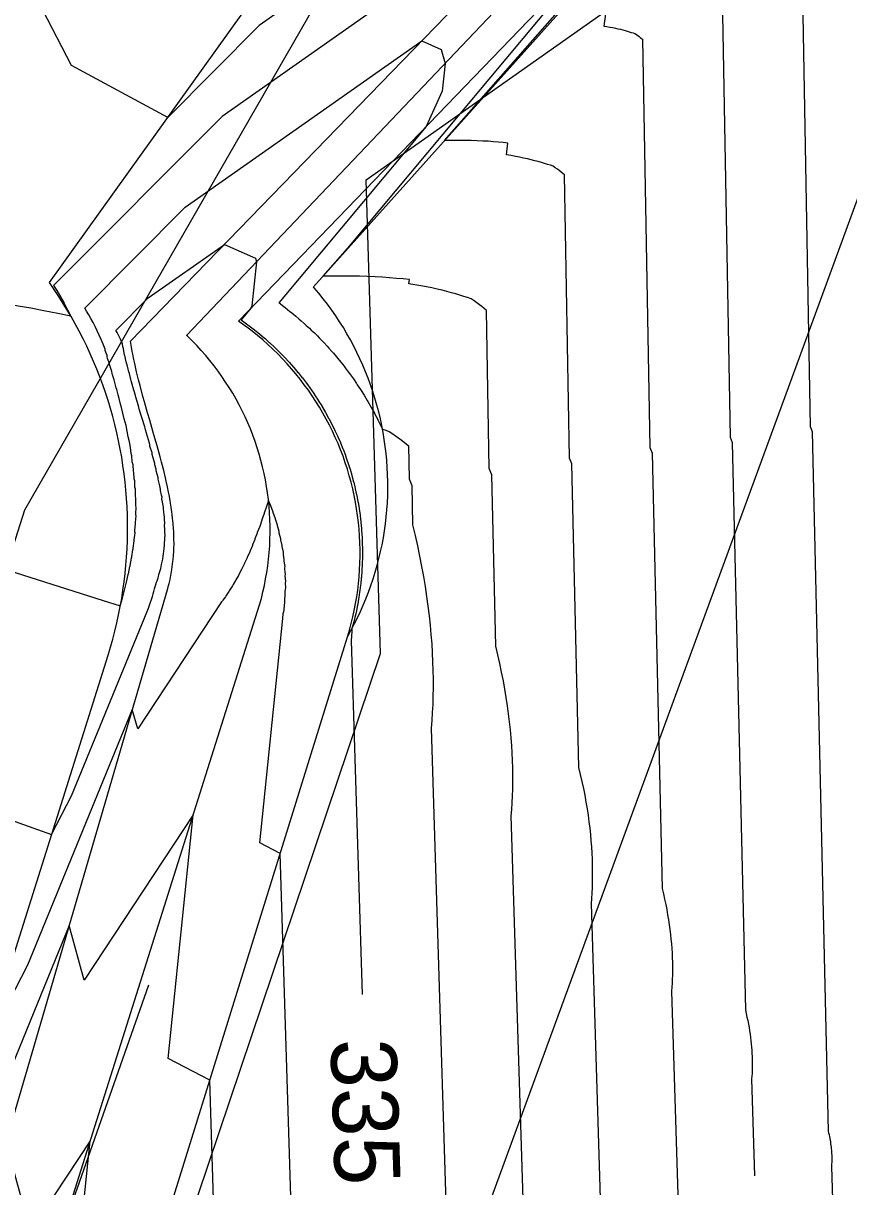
# Model space of a CAD drawing. Extents: x 487096 to 489566, y 221939 to 224454.
# Drawn here: x 488300.7 to 488340.9, y 223456 to 223512.7 of the extents above; entities that cross this region are included whole.
import ezdxf

# ---------------------------------------------------------------- set-up
doc = ezdxf.new("R2010")
doc.units = 0
for name, color, linetype in [('SV_BKLN_BKLN', 7, 'Continuous'), ('SV_BKLN_EARTH_TOP', 7, 'Continuous'), ('SV_PIPE_FLOW', 7, 'Continuous'), ('SV_SURF_INDEX_CONTOUR', 7, 'Continuous'), ('SV_SURF_INTER_CONTOUR', 7, 'Continuous'), ('SV_TREE_TREELN', 7, 'Continuous'), ('SV_WATR_INWETF', 7, 'Continuous'), ('SV_WATR_STREAM', 7, 'Continuous')]:
    doc.layers.add(name, color=color, linetype=linetype)

msp = doc.modelspace()

# ---------------------------------------------------------------- linework, layer by layer
at = {"layer": 'SV_BKLN_BKLN'}
for points in [[(488336.998, 223527.313), (488308.631, 223497.452)], [(488297.876, 223439.045), (488312.09, 223484.017), (488312.184, 223484.327), (488312.27, 223484.639), (488312.348, 223484.953), (488312.419, 223485.269), (488312.481, 223485.587), (488312.536, 223485.906), (488312.583, 223486.226), (488312.622, 223486.547), (488312.653, 223486.87), (488312.676, 223487.192), (488312.691, 223487.516), (488312.699, 223487.839), (488312.698, 223488.163), (488312.689, 223488.487), (488312.672, 223488.81), (488312.647, 223489.133), (488312.614, 223489.455), (488312.573, 223489.776), (488312.525, 223490.096), (488312.468, 223490.415), (488312.404, 223490.732), (488312.331, 223491.047), (488312.251, 223491.361), (488312.163, 223491.672), (488312.068, 223491.982), (488311.965, 223492.289), (488311.854, 223492.593), (488311.736, 223492.894), (488311.611, 223493.193), (488311.478, 223493.488), (488311.338, 223493.78), (488311.19, 223494.068), (488311.036, 223494.352), (488310.875, 223494.633), (488310.706, 223494.91), (488310.531, 223495.182), (488310.35, 223495.45), (488310.161, 223495.713), (488309.967, 223495.972), (488309.766, 223496.225), (488309.558, 223496.474), (488309.345, 223496.718), (488309.126, 223496.956), (488308.901, 223497.188), (488308.67, 223497.415), (488308.631, 223497.452)]]:
    msp.add_lwpolyline(points, dxfattribs=at)
at = {"layer": 'SV_BKLN_EARTH_TOP'}
for points in [[(488337.452, 223525.096), (488314.809, 223499.818)], [(488301.946, 223500.025), (488313.833, 223516.625)], [(488285.935, 223421.955), (488304.8, 223481.874), (488304.918, 223482.263), (488305.029, 223482.654), (488305.132, 223483.047), (488305.227, 223483.442), (488305.314, 223483.839), (488305.393, 223484.238), (488305.465, 223484.638), (488305.529, 223485.039), (488305.585, 223485.442), (488305.632, 223485.846), (488305.672, 223486.25), (488305.704, 223486.655), (488305.728, 223487.061), (488305.744, 223487.467), (488305.752, 223487.874), (488305.752, 223488.28), (488305.744, 223488.687), (488305.728, 223489.093), (488305.704, 223489.498), (488305.672, 223489.904), (488305.632, 223490.308), (488305.584, 223490.712), (488305.529, 223491.114), (488305.465, 223491.516), (488305.393, 223491.916), (488305.314, 223492.315), (488305.226, 223492.712), (488305.131, 223493.107), (488305.028, 223493.5), (488304.918, 223493.891), (488304.799, 223494.28), (488304.673, 223494.666), (488304.54, 223495.05), (488304.399, 223495.432), (488304.25, 223495.81), (488304.095, 223496.185), (488303.931, 223496.557), (488303.761, 223496.926), (488303.583, 223497.292), (488303.398, 223497.654), (488303.206, 223498.012), (488303.007, 223498.366), (488302.801, 223498.717), (488302.588, 223499.063), (488302.368, 223499.405), (488302.142, 223499.743), (488301.946, 223500.025)], [(488316.468, 223482.773), (488316.636, 223483.072), (488316.797, 223483.376), (488316.951, 223483.683), (488317.097, 223483.994), (488317.236, 223484.308), (488317.368, 223484.625), (488317.493, 223484.945), (488317.61, 223485.268), (488317.719, 223485.594), (488317.821, 223485.922), (488317.915, 223486.252), (488318.002, 223486.585), (488318.081, 223486.919), (488318.152, 223487.256), (488318.215, 223487.593), (488318.27, 223487.932), (488318.317, 223488.273), (488318.356, 223488.614), (488318.388, 223488.956), (488318.411, 223489.299), (488318.427, 223489.642), (488318.434, 223489.985), (488318.433, 223490.329), (488318.425, 223490.672), (488318.408, 223491.015), (488318.384, 223491.358), (488318.351, 223491.7), (488318.311, 223492.041), (488318.262, 223492.381), (488318.206, 223492.72), (488318.142, 223493.058), (488318.07, 223493.394), (488317.99, 223493.728), (488317.902, 223494.06), (488317.807, 223494.39), (488317.704, 223494.718), (488317.593, 223495.043), (488317.475, 223495.366), (488317.35, 223495.685), (488317.217, 223496.002), (488317.076, 223496.316), (488316.929, 223496.626), (488316.774, 223496.933), (488316.612, 223497.236), (488316.443, 223497.535), (488316.267, 223497.83), (488316.084, 223498.121), (488315.895, 223498.408), (488315.699, 223498.69), (488315.497, 223498.967), (488315.288, 223499.24), (488315.072, 223499.508), (488314.851, 223499.77), (488314.809, 223499.818)]]:
    msp.add_lwpolyline(points, dxfattribs=at)
at = {"layer": 'SV_PIPE_FLOW'}
msp.add_line((488306.766, 223465.787), (488301.799, 223451.631), dxfattribs=at)
at = {"layer": 'SV_SURF_INDEX_CONTOUR'}
for points in [[(488334.648, 223518.483), (488335.114, 223492.492), (488335.218, 223492.237), (488335.853, 223464.584), (488335.895, 223464.409), (488335.933, 223464.237), (488335.969, 223464.066), (488336.002, 223463.897), (488336.032, 223463.73), (488336.06, 223463.565), (488336.084, 223463.402), (488336.106, 223463.241), (488336.125, 223463.083), (488336.142, 223462.926), (488336.156, 223462.772), (488336.168, 223462.62), (488336.177, 223462.47), (488336.184, 223462.323), (488336.188, 223462.177), (488336.191, 223462.034), (488336.191, 223461.893), (488336.189, 223461.755), (488336.184, 223461.619), (488336.178, 223461.485), (488336.17, 223461.353), (488336.159, 223461.224), (488336.305, 223456.505)], [(488289.043, 223477.783), (488302.048, 223473.132), (488303.017, 223475.013), (488306.702, 223484.002), (488306.764, 223484.157), (488306.82, 223484.308), (488306.872, 223484.452), (488306.919, 223484.591), (488306.962, 223484.726), (488307, 223484.856), (488307.035, 223484.981), (488307.067, 223485.102), (488307.095, 223485.219), (488307.137, 223485.32), (488307.161, 223485.431), (488307.188, 223485.499), (488307.239, 223485.636), (488307.262, 223485.706), (488307.283, 223485.81), (488307.327, 223485.95), (488307.367, 223486.094), (488307.391, 223486.191), (488307.408, 223486.286), (488307.45, 223486.482), (488307.464, 223486.557), (488307.488, 223486.708), (488307.502, 223486.796), (488307.522, 223486.948), (488307.532, 223487.051), (488307.547, 223487.258), (488307.559, 223487.341), (488307.565, 223487.497), (488307.567, 223487.603), (488307.577, 223487.681), (488307.575, 223487.893), (488307.572, 223488), (488307.559, 223488.214), (488307.567, 223488.29), (488307.548, 223488.505), (488307.553, 223488.579), (488307.537, 223488.723), (488307.525, 223488.819), (488307.498, 223489.012), (488307.501, 223489.085), (488307.46, 223489.33), (488307.429, 223489.493), (488307.431, 223489.565), (488307.409, 223489.674), (488307.362, 223489.893), (488307.362, 223489.964), (488307.324, 223490.128), (488307.242, 223490.455), (488307.241, 223490.528), (488307.152, 223490.854), (488307.149, 223490.928), (488307.087, 223491.145), (488307.082, 223491.218), (488306.952, 223491.652), (488306.945, 223491.727), (488306.844, 223492.051), (488306.835, 223492.127), (488306.825, 223492.201), (488306.618, 223492.848), (488306.606, 223492.926), (488306.593, 223493.001), (488306.32, 223493.855), (488306.304, 223493.936), (488306.286, 223494.015), (488306.156, 223494.439), (488306.137, 223494.519), (488306.015, 223494.941), (488305.993, 223495.022), (488305.935, 223495.232), (488305.912, 223495.312), (488305.839, 223495.593), (488305.815, 223495.673), (488305.78, 223495.813), (488305.731, 223496.023), (488305.705, 223496.102), (488305.659, 223496.312), (488305.638, 223496.417), (488305.61, 223496.496), (488305.571, 223496.706), (488305.552, 223496.811), (488305.524, 223496.889), (488305.498, 223497.046), (488305.468, 223497.122), (488305.438, 223497.196), (488305.407, 223497.266), (488305.375, 223497.335), (488305.343, 223497.401), (488305.31, 223497.465), (488305.276, 223497.527), (488305.242, 223497.587), (488305.208, 223497.645), (488305.178, 223497.692), (488306.757, 223499.276), (488310.473, 223501.889), (488311.98, 223501.215), (488312.031, 223501.031), (488311.803, 223498.886), (488311.752, 223498.774), (488311.28, 223498.21), (488311.418, 223498.112), (488311.676, 223497.924), (488311.93, 223497.729), (488312.178, 223497.528), (488312.422, 223497.321), (488312.434, 223497.312), (488312.672, 223497.099), (488312.682, 223497.091), (488312.915, 223496.873), (488312.925, 223496.865), (488313.153, 223496.641), (488313.162, 223496.633), (488313.384, 223496.404), (488313.394, 223496.395), (488313.403, 223496.386), (488313.62, 223496.152), (488313.629, 223496.143), (488313.84, 223495.903), (488313.849, 223495.894), (488314.053, 223495.65), (488314.063, 223495.64), (488314.261, 223495.391), (488314.27, 223495.38), (488314.463, 223495.127), (488314.472, 223495.116), (488314.481, 223495.105), (488314.666, 223494.848), (488314.676, 223494.836), (488314.855, 223494.574), (488314.864, 223494.562), (488315.037, 223494.297), (488315.045, 223494.284), (488315.212, 223494.015), (488315.22, 223494.002), (488315.38, 223493.729), (488315.388, 223493.715), (488315.397, 223493.701), (488315.55, 223493.425), (488315.558, 223493.41), (488315.704, 223493.131), (488315.712, 223493.115), (488315.851, 223492.833), (488315.859, 223492.817), (488315.991, 223492.532), (488315.999, 223492.516), (488316.123, 223492.228), (488316.131, 223492.211), (488316.248, 223491.921), (488316.256, 223491.903), (488316.366, 223491.611), (488316.373, 223491.592), (488316.476, 223491.298), (488316.482, 223491.278), (488316.489, 223491.258), (488316.584, 223490.962), (488316.591, 223490.941), (488316.678, 223490.644), (488316.684, 223490.621), (488316.765, 223490.323), (488316.77, 223490.3), (488316.843, 223490.001), (488316.849, 223489.977), (488316.914, 223489.677), (488316.919, 223489.652), (488316.977, 223489.351), (488316.982, 223489.325), (488317.032, 223489.024), (488317.036, 223488.997), (488317.08, 223488.696), (488317.083, 223488.667), (488317.119, 223488.366), (488317.122, 223488.337), (488317.15, 223488.037), (488317.153, 223488.006), (488317.174, 223487.706), (488317.176, 223487.674), (488317.189, 223487.376), (488317.191, 223487.341), (488317.197, 223487.045), (488317.198, 223487.009), (488317.197, 223486.967), (488317.196, 223486.676), (488317.195, 223486.631), (488317.187, 223486.344), (488317.185, 223486.294), (488317.17, 223486.011), (488317.166, 223485.957), (488317.145, 223485.68), (488317.139, 223485.62), (488317.112, 223485.349), (488317.103, 223485.281), (488317.071, 223485.018), (488317.059, 223484.941), (488317.022, 223484.689), (488317.006, 223484.598), (488316.965, 223484.362), (488316.942, 223484.25), (488316.9, 223484.035), (488316.867, 223483.889), (488316.827, 223483.711), (488316.774, 223483.496), (488316.747, 223483.388), (488316.686, 223483.167), (488316.677, 223483.027), (488316.642, 223482.583), (488317.175, 223465.337)]]:
    msp.add_lwpolyline(points, dxfattribs=at)
at = {"layer": 'SV_SURF_INTER_CONTOUR'}
for points in [[(488329.706, 223521.724), (488310.366, 223508.123), (488302.146, 223499.88), (488302.3, 223499.635), (488302.48, 223499.335), (488302.657, 223499.024), (488302.832, 223498.701), (488302.988, 223498.398), (488302.35, 223498.527), (488301.679, 223498.657), (488301.038, 223498.776), (488300.425, 223498.885), (488299.926, 223498.969), (488299.677, 223499.552), (488291.289, 223504.08), (488279.6, 223526.573)], [(488330.243, 223525.257), (488312.17, 223512.546), (488307.71, 223508.074), (488303.018, 223510.607), (488297.411, 223521.398)], [(488329.06, 223446.889), (488328.352, 223469.768), (488328.373, 223470.023), (488328.389, 223470.282), (488328.402, 223470.547), (488328.41, 223470.816), (488328.414, 223471.09), (488328.414, 223471.368), (488328.41, 223471.65), (488328.401, 223471.938), (488328.387, 223472.229), (488328.369, 223472.525), (488328.346, 223472.826), (488328.318, 223473.13), (488328.285, 223473.439), (488328.247, 223473.753), (488328.204, 223474.07), (488328.155, 223474.392), (488328.101, 223474.717), (488328.042, 223475.047), (488327.977, 223475.381), (488327.906, 223475.718), (488327.829, 223476.06), (488327.747, 223476.405), (488327.407, 223491.189), (488327.289, 223491.477), (488327.042, 223505.277), (488326.963, 223505.345), (488326.879, 223505.414), (488326.789, 223505.484), (488326.693, 223505.554), (488326.591, 223505.624), (488326.483, 223505.695), (488326.353, 223505.741), (488326.216, 223505.786), (488326.072, 223505.832), (488325.92, 223505.877), (488325.762, 223505.922), (488325.596, 223505.966), (488325.423, 223506.009), (488325.241, 223506.051), (488325.052, 223506.093), (488324.854, 223506.133), (488324.649, 223506.173), (488324.435, 223506.211), (488324.212, 223506.247), (488324.283, 223506.827), (488324.056, 223506.851), (488323.821, 223506.873), (488323.576, 223506.892), (488323.322, 223506.91), (488323.058, 223506.924), (488322.784, 223506.937), (488322.501, 223506.946), (488322.207, 223506.952), (488321.902, 223506.956), (488321.586, 223506.955), (488321.26, 223506.951), (488321.198, 223506.95), (488337.218, 223525.176)], [(488340.246, 223451.02), (488340.063, 223456.953), (488340.068, 223457.019), (488340.072, 223457.086), (488340.076, 223457.155), (488340.078, 223457.224), (488340.079, 223457.295), (488340.079, 223457.367), (488340.078, 223457.441), (488340.076, 223457.515), (488340.072, 223457.591), (488340.067, 223457.668), (488340.061, 223457.746), (488340.054, 223457.825), (488340.046, 223457.905), (488340.036, 223457.986), (488340.024, 223458.068), (488340.012, 223458.152), (488339.998, 223458.236), (488339.982, 223458.322), (488339.966, 223458.408), (488339.947, 223458.496), (488339.927, 223458.584), (488339.906, 223458.674), (488339.124, 223492.76), (488339.026, 223492.999), (488338.453, 223524.924)], [(488325.331, 223445.512), (488324.449, 223474.039), (488324.474, 223474.357), (488324.495, 223474.681), (488324.51, 223475.011), (488324.521, 223475.346), (488324.526, 223475.688), (488324.526, 223476.035), (488324.52, 223476.387), (488324.509, 223476.745), (488324.492, 223477.109), (488324.47, 223477.478), (488324.441, 223477.852), (488324.406, 223478.232), (488324.365, 223478.618), (488324.318, 223479.008), (488324.264, 223479.404), (488324.203, 223479.805), (488324.136, 223480.211), (488324.062, 223480.622), (488323.98, 223481.038), (488323.892, 223481.459), (488323.796, 223481.885), (488323.693, 223482.316), (488323.502, 223490.665), (488323.377, 223490.97), (488323.239, 223498.673), (488323.134, 223498.765), (488323.021, 223498.857), (488322.901, 223498.95), (488322.772, 223499.043), (488322.636, 223499.137), (488322.492, 223499.232), (488322.318, 223499.293), (488322.135, 223499.354), (488321.943, 223499.415), (488321.741, 223499.475), (488321.53, 223499.534), (488321.308, 223499.593), (488321.076, 223499.651), (488320.834, 223499.708), (488320.581, 223499.764), (488320.318, 223499.818), (488320.043, 223499.87), (488319.757, 223499.921), (488319.459, 223499.969), (488319.484, 223500.171), (488319.175, 223500.203), (488318.854, 223500.233), (488318.52, 223500.259), (488318.173, 223500.283), (488317.813, 223500.303), (488317.44, 223500.32), (488317.053, 223500.333), (488316.652, 223500.342), (488316.236, 223500.346), (488315.805, 223500.346), (488315.36, 223500.34), (488315.275, 223500.339), (488316.477, 223501.706), (488328.849, 223516.501)], [(488329.081, 223513.483), (488328.964, 223512.525), (488329.112, 223512.501), (488329.255, 223512.475), (488329.391, 223512.449), (488329.522, 223512.423), (488329.648, 223512.395), (488329.769, 223512.367), (488329.884, 223512.338), (488329.994, 223512.309), (488330.1, 223512.279), (488330.2, 223512.249), (488330.296, 223512.219), (488330.387, 223512.188), (488330.473, 223512.158), (488330.545, 223512.111), (488330.613, 223512.064), (488330.676, 223512.018), (488330.736, 223511.971), (488330.792, 223511.925), (488330.845, 223511.88), (488331.202, 223491.985), (488331.313, 223491.713), (488331.8, 223470.495), (488331.862, 223470.235), (488331.92, 223469.977), (488331.973, 223469.723), (488332.022, 223469.472), (488332.067, 223469.224), (488332.108, 223468.978), (488332.144, 223468.736), (488332.177, 223468.497), (488332.205, 223468.261), (488332.23, 223468.028), (488332.251, 223467.799), (488332.269, 223467.573), (488332.282, 223467.35), (488332.292, 223467.13), (488332.299, 223466.914), (488332.302, 223466.701), (488332.302, 223466.491), (488332.299, 223466.285), (488332.293, 223466.083), (488332.284, 223465.884), (488332.271, 223465.688), (488332.256, 223465.496), (488332.789, 223448.266)], [(488297.761, 223486.691), (488304.559, 223484.535), (488305.399, 223484.269), (488305.504, 223484.647), (488305.607, 223485.043), (488305.698, 223485.425), (488305.701, 223485.433), (488305.783, 223485.805), (488305.785, 223485.812), (488305.79, 223485.825), (488305.793, 223485.832), (488305.866, 223486.197), (488305.871, 223486.214), (488305.876, 223486.231), (488305.879, 223486.243), (488305.945, 223486.603), (488305.951, 223486.631), (488305.953, 223486.641), (488305.956, 223486.663), (488306.014, 223487.018), (488306.017, 223487.043), (488306.019, 223487.059), (488306.022, 223487.093), (488306.072, 223487.444), (488306.073, 223487.473), (488306.073, 223487.492), (488306.115, 223487.836), (488306.114, 223487.878), (488306.114, 223487.899), (488306.111, 223487.941), (488306.144, 223488.282), (488306.14, 223488.329), (488306.165, 223488.661), (488306.162, 223488.695), (488306.159, 223488.717), (488306.152, 223488.762), (488306.169, 223489.091), (488306.159, 223489.152), (488306.151, 223489.192), (488306.16, 223489.516), (488306.155, 223489.545), (488306.142, 223489.603), (488306.143, 223489.921), (488306.133, 223489.966), (488306.11, 223490.057), (488306.104, 223490.373), (488306.078, 223490.468), (488306.064, 223490.778), (488306.045, 223490.845), (488306.025, 223491.148), (488305.983, 223491.286), (488305.957, 223491.586), (488305.923, 223491.694), (488305.89, 223491.989), (488305.852, 223492.274), (488305.778, 223492.505), (488305.733, 223492.79), (488305.684, 223493.067), (488305.581, 223493.39), (488305.524, 223493.67), (488305.464, 223493.941), (488305.412, 223494.11), (488305.346, 223494.378), (488305.296, 223494.55), (488305.226, 223494.815), (488305.202, 223494.903), (488305.127, 223495.162), (488305.096, 223495.282), (488305.017, 223495.537), (488305.002, 223495.598), (488304.981, 223495.69), (488304.898, 223495.94), (488304.878, 223496.034), (488304.868, 223496.08), (488304.782, 223496.326), (488304.764, 223496.422), (488304.756, 223496.469), (488304.667, 223496.71), (488304.655, 223496.783), (488304.563, 223497.018), (488304.469, 223497.246), (488304.372, 223497.466), (488304.274, 223497.679), (488304.173, 223497.885), (488304.071, 223498.083), (488303.967, 223498.275), (488303.861, 223498.461), (488303.754, 223498.64), (488303.662, 223498.786), (488308.561, 223503.699), (488320.089, 223511.807), (488321.032, 223511.385), (488321.22, 223510.704), (488321.076, 223509.349), (488320.301, 223507.638), (488313.117, 223499.047), (488313.183, 223499), (488313.307, 223498.91), (488313.429, 223498.816), (488313.548, 223498.72), (488313.665, 223498.621), (488313.692, 223498.6), (488313.842, 223498.484), (488313.954, 223498.385), (488314.104, 223498.264), (488314.21, 223498.165), (488314.36, 223498.038), (488314.461, 223497.939), (488314.611, 223497.807), (488314.706, 223497.709), (488314.856, 223497.571), (488315.008, 223497.425), (488315.095, 223497.331), (488315.248, 223497.178), (488315.329, 223497.085), (488315.481, 223496.926), (488315.557, 223496.836), (488315.709, 223496.67), (488315.779, 223496.582), (488315.93, 223496.41), (488315.995, 223496.324), (488316.146, 223496.145), (488316.3, 223495.953), (488316.355, 223495.877), (488316.508, 223495.677), (488316.558, 223495.604), (488316.711, 223495.397), (488316.755, 223495.329), (488316.907, 223495.113), (488316.946, 223495.05), (488317.097, 223494.825), (488317.13, 223494.768), (488317.28, 223494.534), (488317.433, 223494.283), (488317.457, 223494.24), (488317.609, 223493.979), (488317.627, 223493.944), (488317.778, 223493.671), (488317.791, 223493.645), (488317.941, 223493.36), (488317.949, 223493.344), (488318.097, 223493.047), (488318.1, 223493.041), (488318.175, 223492.882), (488318.284, 223492.846), (488318.502, 223492.769), (488318.682, 223492.651), (488318.852, 223492.533), (488319.013, 223492.416), (488319.163, 223492.299), (488319.305, 223492.184), (488319.436, 223492.07), (488319.465, 223490.463), (488319.596, 223490.141), (488319.64, 223488.226), (488319.764, 223487.71), (488319.878, 223487.2), (488319.984, 223486.696), (488320.081, 223486.197), (488320.17, 223485.705), (488320.251, 223485.218), (488320.324, 223484.738), (488320.388, 223484.264), (488320.445, 223483.796), (488320.494, 223483.334), (488320.536, 223482.879), (488320.57, 223482.43), (488320.598, 223481.988), (488320.618, 223481.553), (488320.631, 223481.124), (488320.638, 223480.701), (488320.638, 223480.286), (488320.631, 223479.877), (488320.619, 223479.475), (488320.6, 223479.08), (488320.576, 223478.692), (488320.545, 223478.311), (488321.602, 223444.135)], [(488314.145, 223441.381), (488313.191, 223472.214), (488312.2, 223472.734), (488313.325, 223483.666), (488313.34, 223483.907), (488313.366, 223483.993), (488313.39, 223484.079), (488313.397, 223484.323), (488313.418, 223484.406), (488313.419, 223484.655), (488313.437, 223484.734), (488313.431, 223484.989), (488313.446, 223485.064), (488313.459, 223485.139), (488313.445, 223485.396), (488313.456, 223485.467), (488313.434, 223485.73), (488313.442, 223485.796), (488313.413, 223486.065), (488313.419, 223486.126), (488313.424, 223486.188), (488313.385, 223486.458), (488313.389, 223486.515), (488313.342, 223486.79), (488313.343, 223486.841), (488313.344, 223486.893), (488313.288, 223487.168), (488313.287, 223487.214), (488313.222, 223487.496), (488313.22, 223487.536), (488313.146, 223487.823), (488313.144, 223487.857), (488313.14, 223487.891), (488313.056, 223488.178), (488313.053, 223488.205), (488312.959, 223488.498), (488312.956, 223488.519), (488312.85, 223488.818), (488312.848, 223488.832), (488312.845, 223488.845), (488312.73, 223489.143), (488312.729, 223489.149), (488312.618, 223489.412), (488312.523, 223489.122), (488312.524, 223489.117), (488312.413, 223488.796), (488312.413, 223488.781), (488312.302, 223488.471), (488312.302, 223488.449), (488312.189, 223488.148), (488312.189, 223488.134), (488312.075, 223487.847), (488312.072, 223487.812), (488311.958, 223487.534), (488311.955, 223487.514), (488311.84, 223487.248), (488311.835, 223487.213), (488311.718, 223486.958), (488311.707, 223486.906), (488311.59, 223486.659), (488311.583, 223486.631), (488311.57, 223486.587), (488311.451, 223486.348), (488311.434, 223486.301), (488311.315, 223486.072), (488311.305, 223486.047), (488311.185, 223485.829), (488311.154, 223485.757), (488311.034, 223485.548), (488311.015, 223485.51), (488310.895, 223485.31), (488310.863, 223485.251), (488310.742, 223485.06), (488310.705, 223484.999), (488310.685, 223484.967), (488310.564, 223484.785), (488310.518, 223484.72), (488310.397, 223484.547), (488310.372, 223484.514), (488310.332, 223484.463), (488306.247, 223478.276), (488305.984, 223479.23), (488300.871, 223466.76), (488298.737, 223462.617)], [(488320.594, 223209.107), (488317.309, 223255.078), (488319.07, 223277.176), (488313.215, 223307.684), (488312.007, 223315.85), (488310.013, 223331.587), (488309.153, 223355.183), (488306.035, 223366.994), (488308.318, 223385.059), (488309.639, 223426.754), (488310.11, 223434.831), (488310.416, 223440.004), (488309.761, 223461.164), (488307.732, 223462.227), (488308.954, 223474.096), (488303.636, 223466.041), (488302.905, 223468.698), (488298.726, 223458.507), (488295.426, 223452.101), (488285.665, 223455.591), (488279.114, 223460.734), (488240.248, 223486.418)], [(488316.219, 223209.854), (488313.699, 223245.125), (488316.327, 223278.11), (488311.228, 223304.679), (488309.711, 223314.936), (488307.206, 223334.704), (488306.474, 223354.761), (488302.863, 223368.44), (488304.74, 223383.289), (488306.265, 223431.434), (488306.521, 223435.818), (488306.687, 223438.627), (488306.332, 223450.114), (488303.265, 223451.72), (488303.933, 223458.21), (488301.025, 223453.805), (488299.825, 223458.167), (488296.581, 223450.253), (488292.115, 223441.585), (488285.759, 223443.858), (488281.493, 223447.207), (488226.844, 223483.321)]]:
    msp.add_lwpolyline(points, dxfattribs=at)
at = {"layer": 'SV_TREE_TREELN'}
msp.add_lwpolyline([(488372.848, 223524.962), (488345.591, 223515.782), (488315.545, 223433.799)], dxfattribs=at)
at = {"layer": 'SV_WATR_INWETF'}
for points in [[(488392.951, 223538.467), (488377.591, 223540.374), (488348.653, 223536.588), (488322.282, 223526.421), (488300.731, 223488.93), (488278.082, 223417.696)], [(488318.074, 223481.951), (488317.38, 223505.041), (488351.676, 223529.226), (488396.355, 223531.52)], [(488301.311, 223432.187), (488318.074, 223481.951)]]:
    msp.add_lwpolyline(points, dxfattribs=at)
at = {"layer": 'SV_WATR_STREAM'}
for points in [[(488336.137, 223528.357), (488305.899, 223497.172)], [(488337.216, 223525.176), (488311.151, 223498.151)], [(488302.259, 223436.992), (488316.468, 223482.773), (488316.563, 223483.091), (488316.649, 223483.41), (488316.728, 223483.732), (488316.799, 223484.056), (488316.863, 223484.382), (488316.918, 223484.708), (488316.966, 223485.036), (488317.006, 223485.366), (488317.037, 223485.696), (488317.061, 223486.026), (488317.077, 223486.357), (488317.085, 223486.689), (488317.084, 223487.02), (488317.076, 223487.352), (488317.06, 223487.683), (488317.036, 223488.013), (488317.003, 223488.343), (488316.963, 223488.672), (488316.915, 223489), (488316.859, 223489.327), (488316.795, 223489.652), (488316.724, 223489.976), (488316.644, 223490.298), (488316.557, 223490.618), (488316.462, 223490.935), (488316.36, 223491.251), (488316.25, 223491.563), (488316.132, 223491.873), (488316.007, 223492.18), (488315.874, 223492.484), (488315.735, 223492.785), (488315.588, 223493.082), (488315.434, 223493.375), (488315.273, 223493.665), (488315.105, 223493.951), (488314.93, 223494.233), (488314.748, 223494.51), (488314.56, 223494.783), (488314.365, 223495.051), (488314.164, 223495.314), (488313.956, 223495.573), (488313.743, 223495.826), (488313.523, 223496.075), (488313.297, 223496.317), (488313.066, 223496.555), (488312.829, 223496.786), (488312.586, 223497.012), (488312.338, 223497.232), (488312.085, 223497.446), (488311.826, 223497.654), (488311.563, 223497.855), (488311.295, 223498.05), (488311.151, 223498.151)], [(488289.13, 223421.588), (488307.709, 223485.128), (488307.749, 223485.272), (488307.774, 223485.368), (488307.821, 223485.561), (488307.842, 223485.657), (488307.88, 223485.85), (488307.914, 223486.043), (488307.933, 223486.172), (488307.965, 223486.431), (488307.975, 223486.528), (488307.992, 223486.723), (488308.004, 223486.918), (488308.009, 223487.048), (488308.015, 223487.309), (488308.014, 223487.505), (488308.011, 223487.636), (488308.001, 223487.898), (488307.993, 223488.029), (488307.973, 223488.292), (488307.947, 223488.555), (488307.926, 223488.731), (488307.911, 223488.848), (488307.878, 223489.083), (488307.847, 223489.282), (488307.824, 223489.414), (488307.776, 223489.679), (488307.751, 223489.811), (488307.697, 223490.077), (488307.639, 223490.343), (488307.598, 223490.52), (488307.512, 223490.875), (488307.41, 223491.275), (488307.339, 223491.541), (488307.192, 223492.075), (488307.039, 223492.61), (488306.832, 223493.322), (488306.728, 223493.679), (488306.576, 223494.213), (488306.501, 223494.48), (488306.358, 223495.013), (488306.29, 223495.28), (488306.192, 223495.679), (488306.102, 223496.078), (488306.06, 223496.277), (488306.007, 223496.543), (488305.982, 223496.675), (488305.947, 223496.874), (488305.899, 223497.172)]]:
    msp.add_lwpolyline(points, dxfattribs=at)

# ---------------------------------------------------------------- texts
at = {"layer": 'SV_SURF_INDEX_CONTOUR'}
msp.add_text('335', height=3.2, rotation=271.7716, dxfattribs=at).set_placement((488315.642, 223463.14))

doc.saveas('drawing.dxf')
